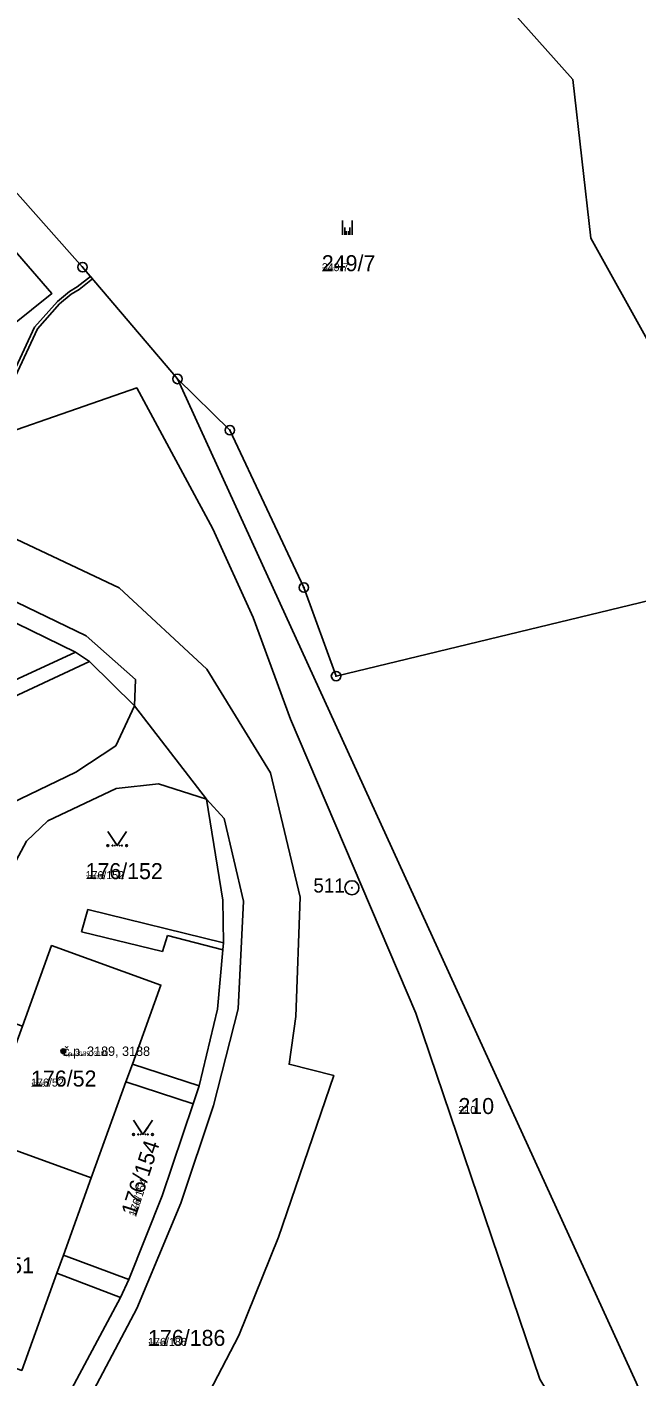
# Model space of a CAD drawing. Extents: x -759873 to -758487, y -975024 to -973516.
# Drawn here: x -759165.8 to -759101, y -974781.5 to -974638.1 of the extents above; entities that cross this region are included whole.
import ezdxf

# ---------------------------------------------------------------- set-up
doc = ezdxf.new("R2010")
doc.units = 0
for name, color, linetype in [('KAT_02_hranice parcel', 7, 'Continuous'), ('KAT_03_1000_st čísla parcelní', 7, 'Continuous'), ('KAT_03_1000_čísla parcelní', 7, 'Continuous'), ('KAT_03_1000_čísla popisná', 7, 'Continuous'), ('KAT_03_250_st čísla parcelní', 7, 'Continuous'), ('KAT_03_250_čísla parcelní', 7, 'Continuous'), ('KAT_03_250_čísla popisná', 7, 'Continuous'), ('KAT_03_500_st čísla parcelní', 7, 'Continuous'), ('KAT_03_500_čísla parcelní', 7, 'Continuous'), ('KAT_03_500_čísla popisná', 7, 'Continuous'), ('KAT_04_vnitřní kresba', 7, 'Continuous'), ('KAT_05_1000_značky kultur', 7, 'Continuous'), ('KAT_05_250_značky kultur', 7, 'Continuous'), ('KAT_05_500_značky kultur', 7, 'Continuous'), ('KAT_07_1000_značky budov', 7, 'Continuous'), ('KAT_07_250_značky budov', 7, 'Continuous'), ('KAT_07_500_značky budov', 7, 'Continuous'), ('KAT_10_věcná břemena', 7, 'Continuous'), ('KAT_11_značky bodu BP', 7, 'Continuous'), ('KAT_14_plocha_budovy', 7, 'Continuous'), ('KAT_14_plocha_pozemek', 7, 'Continuous')]:
    doc.layers.add(name, color=color, linetype=linetype)

msp = doc.modelspace()

# ---------------------------------------------------------------- linework, layer by layer
at = {"layer": 'KAT_02_hranice parcel'}
for p, q in [((-759179.67, -974713.25), (-759160.58, -974704.45)), ((-759159.12, -974705.45), (-759160.58, -974704.45)), ((-759159.12, -974705.45), (-759154.33, -974710.16)), ((-759154.33, -974710.16), (-759146.66, -974720.07)), ((-759148.07, -974752.44), (-759147.45, -974750.53)), ((-759158.92, -974760.3), (-759170.54, -974756.1)), ((-759155.8, -974773.02), (-759154.93, -974771.11))]:
    msp.add_line(p, q, dxfattribs=at)
for points in [[(-759121.31, -974628.39), (-759107.72, -974643.63), (-759105.8, -974660.49), (-759087.3, -974693.73), (-759084.37, -974695.3)], [(-759179.97, -974642.79), (-759178.7, -974648.26), (-759178.66, -974648.44), (-759163.12, -974666.36), (-759176.12, -974676.76)], [(-759149.76, -974675.44), (-759159.84, -974663.56), (-759172.86, -974648.93), (-759179.97, -974642.79)], [(-759084.37, -974695.3), (-759132.9, -974707), (-759136.32, -974697.59), (-759144.18, -974680.88), (-759149.76, -974675.44)], [(-759097.35, -974808.06), (-759096.43, -974792.71), (-759100.98, -974782.04), (-759149.76, -974675.44)], [(-759175.68, -974683.88), (-759154.09, -974676.39), (-759145.99, -974691.36), (-759141.71, -974700.76), (-759137.73, -974711.57), (-759124.4, -974742.82), (-759111.25, -974781.7), (-759103.79, -974793.94), (-759101.42, -974795.61)], [(-759182.08, -974824.14), (-759181.15, -974823.29), (-759171.83, -974813.43), (-759165.02, -974804.41), (-759157.43, -974793.66), (-759153.11, -974796.03), (-759143.25, -974777.05), (-759139.01, -974766.6), (-759133.15, -974749.42), (-759137.89, -974748.23), (-759137.17, -974743.17), (-759136.73, -974730.48), (-759139.87, -974717.29), (-759146.64, -974706.25), (-759155.94, -974697.62), (-759168.19, -974691.87), (-759181.09, -974689.78), (-759191.31, -974690.97), (-759198.55, -974692.98), (-759199.06, -974691.99)], [(-759160.58, -974704.45), (-759170.07, -974699.86), (-759180.57, -974698.08), (-759189.73, -974699.13), (-759195.81, -974700.76)], [(-759297.2, -974770.95), (-759269.53, -974757.78), (-759268.81, -974757.44), (-759237.44, -974742.52), (-759232.51, -974740.14), (-759189.23, -974719.52), (-759188.5, -974719.17), (-759159.12, -974705.45)], [(-759301.24, -974780.99), (-759301.03, -974781.35), (-759293.44, -974780.74), (-759288.26, -974778.87), (-759268.89, -974769.51), (-759250.85, -974760.82), (-759247.34, -974759.1), (-759236.73, -974753.99), (-759224.73, -974748.18), (-759206.51, -974739.34), (-759188.27, -974730.61), (-759177.27, -974725.26), (-759160.55, -974717.22), (-759156.31, -974714.42), (-759154.33, -974710.16)], [(-759146.66, -974720.07), (-759151.76, -974718.46), (-759156.28, -974718.94), (-759163.54, -974722.39), (-759165.81, -974724.55), (-759167.17, -974727.13)], [(-759147.45, -974750.53), (-759145.5, -974742.38), (-759144.92, -974736.07), (-759144.85, -974735.33), (-759144.92, -974730.81), (-759146.66, -974720.07)], [(-759147.45, -974750.53), (-759154.55, -974748.22), (-759151.52, -974739.83), (-759163.14, -974735.63), (-759166.23, -974744.18), (-759171.94, -974742.21)], [(-759158.92, -974760.3), (-759155.23, -974750.11), (-759148.07, -974752.44)], [(-759154.93, -974771.11), (-759151.37, -974762.2), (-759148.07, -974752.44)], [(-759154.93, -974771.11), (-759161.88, -974768.5), (-759158.92, -974760.3)], [(-759179.16, -974764.89), (-759174.26, -974766.42), (-759177.93, -974776.57), (-759166.31, -974780.76), (-759162.58, -974770.43), (-759155.8, -974773.02)], [(-759178.71, -974808.89), (-759171.77, -974799.76), (-759171.33, -974799.09), (-759163.17, -974786.79), (-759155.8, -974773.02)]]:
    msp.add_lwpolyline(points, dxfattribs=at)
at = {"layer": 'KAT_03_1000_čísla popisná'}
msp.add_circle((-759161.89, -974746.85), 0.25, dxfattribs=at)
at = {"layer": 'KAT_03_250_čísla popisná'}
msp.add_circle((-759161.89, -974746.85), 0.0625, dxfattribs=at)
at = {"layer": 'KAT_03_500_čísla popisná'}
msp.add_circle((-759161.89, -974746.85), 0.125, dxfattribs=at)
at = {"layer": 'KAT_04_vnitřní kresba'}
for p, q in [((-759169.64, -974697.85), (-759159.46, -974702.72)), ((-759159.46, -974702.72), (-759154.22, -974707.35)), ((-759154.33, -974710.16), (-759154.22, -974707.35)), ((-759146.66, -974720.07), (-759144.79, -974722.14)), ((-759144.79, -974722.14), (-759142.73, -974730.92)), ((-759143.3, -974742.35), (-759142.73, -974730.92)), ((-759159.94, -974734.16), (-759159.3, -974731.81)), ((-759159.3, -974731.81), (-759144.85, -974735.33)), ((-759159.94, -974734.16), (-759151.34, -974736.25)), ((-759151.34, -974736.25), (-759150.83, -974734.56)), ((-759150.83, -974734.56), (-759144.92, -974736.07)), ((-759145.92, -974752.61), (-759143.3, -974742.35)), ((-759155.23, -974750.11), (-759154.55, -974748.22)), ((-759149.41, -974762.99), (-759145.92, -974752.61)), ((-759154.08, -974774.19), (-759149.41, -974762.99)), ((-759162.58, -974770.43), (-759161.88, -974768.5)), ((-759161.31, -974787.79), (-759154.08, -974774.19))]:
    msp.add_line(p, q, dxfattribs=at)
at = {"layer": 'KAT_05_1000_značky kultur'}
for p, q in [((-759132.2, -974660.11), (-759132.2, -974658.61)), ((-759131.2, -974660.11), (-759131.2, -974658.61))]:
    msp.add_line(p, q, dxfattribs=at)
for points in [[(-759157.16, -974723.51), (-759156.16, -974725.01), (-759155.16, -974723.51)], [(-759154.42, -974754.19), (-759153.42, -974755.69), (-759152.42, -974754.19)]]:
    msp.add_lwpolyline(points, dxfattribs=at)
for centre in [(-759157.16, -974725.01), (-759155.16, -974725.01), (-759154.42, -974755.69), (-759152.42, -974755.69)]:
    msp.add_circle(centre, 0.1, dxfattribs=at)
at = {"layer": 'KAT_05_250_značky kultur'}
for p, q in [((-759131.82, -974660.11), (-759131.82, -974659.73)), ((-759131.57, -974660.11), (-759131.57, -974659.73))]:
    msp.add_line(p, q, dxfattribs=at)
for points in [[(-759156.41, -974724.63), (-759156.16, -974725.01), (-759155.91, -974724.63)], [(-759153.67, -974755.31), (-759153.42, -974755.69), (-759153.17, -974755.31)]]:
    msp.add_lwpolyline(points, dxfattribs=at)
for centre in [(-759156.41, -974725.01), (-759155.91, -974725.01), (-759153.67, -974755.69), (-759153.17, -974755.69)]:
    msp.add_circle(centre, 0.025, dxfattribs=at)
at = {"layer": 'KAT_05_500_značky kultur'}
for p, q in [((-759131.95, -974660.11), (-759131.95, -974659.36)), ((-759131.45, -974660.11), (-759131.45, -974659.36))]:
    msp.add_line(p, q, dxfattribs=at)
for points in [[(-759156.66, -974724.26), (-759156.16, -974725.01), (-759155.66, -974724.26)], [(-759153.92, -974754.94), (-759153.42, -974755.69), (-759152.92, -974754.94)]]:
    msp.add_lwpolyline(points, dxfattribs=at)
for centre in [(-759156.66, -974725.01), (-759155.66, -974725.01), (-759153.92, -974755.69), (-759152.92, -974755.69)]:
    msp.add_circle(centre, 0.05, dxfattribs=at)
at = {"layer": 'KAT_07_1000_značky budov'}
msp.add_circle((-759161.9, -974746.85), 0.175, dxfattribs=at)
at = {"layer": 'KAT_07_250_značky budov'}
msp.add_circle((-759161.89, -974746.85), 0.0437, dxfattribs=at)
at = {"layer": 'KAT_07_500_značky budov'}
msp.add_circle((-759161.89, -974746.85), 0.0875, dxfattribs=at)
at = {"layer": 'KAT_10_věcná břemena'}
msp.add_lwpolyline([(-759160.41, -974665.65), (-759161.25, -974666.14), (-759162.52, -974667.2), (-759164.95, -974669.93), (-759168.45, -974677.51), (-759169.21, -974679.17), (-759170.1, -974681.94), (-759169.7, -974681.8), (-759168.89, -974679.29), (-759168.13, -974677.65), (-759164.65, -974670.12), (-759162.29, -974667.47), (-759161.06, -974666.44), (-759160.19, -974665.93), (-759158.78, -974664.81), (-759159.01, -974664.54)], close=True, dxfattribs=at)
at = {"layer": 'KAT_11_značky bodu BP'}
for centre, radius in [((-759159.84, -974663.56), 0.5), ((-759159.84, -974663.56), 0.0303), ((-759149.76, -974675.44), 0.5), ((-759149.76, -974675.44), 0.0303), ((-759144.18, -974680.88), 0.5), ((-759144.18, -974680.88), 0.0303), ((-759136.32, -974697.59), 0.5), ((-759136.32, -974697.59), 0.0303), ((-759132.9, -974707), 0.5), ((-759132.9, -974707), 0.0303), ((-759131.21, -974729.49), 0.75), ((-759131.21, -974729.49), 0.03)]:
    msp.add_circle(centre, radius, dxfattribs=at)
at = {"layer": 'KAT_14_plocha_budovy'}
msp.add_lwpolyline([(-759154.55, -974748.22), (-759151.52, -974739.83), (-759163.14, -974735.63), (-759166.23, -974744.18), (-759166.93, -974746.13), (-759170.54, -974756.1), (-759173.59, -974764.55), (-759174.26, -974766.42), (-759177.93, -974776.57), (-759166.31, -974780.76), (-759162.58, -974770.43), (-759161.88, -974768.5), (-759158.92, -974760.3), (-759155.23, -974750.11)], close=True, dxfattribs=at)
at = {"layer": 'KAT_14_plocha_pozemek'}
for points in [[(-759179.97, -974642.79), (-759172.86, -974648.93), (-759159.84, -974663.56), (-759149.76, -974675.44), (-759144.18, -974680.88), (-759136.32, -974697.59), (-759132.9, -974707), (-759084.37, -974695.3), (-759087.3, -974693.73), (-759105.8, -974660.49), (-759107.72, -974643.63), (-759121.31, -974628.39), (-759134.04, -974629.13), (-759146.2, -974621.75), (-759148.58, -974619.46), (-759181.41, -974628.97), (-759180.71, -974639.63)], [(-759050.14, -974687.05), (-759051.77, -974677.63), (-759055.52, -974672.89), (-759062.41, -974666.25), (-759071.5, -974656.72), (-759078.54, -974653.94), (-759098.65, -974634.53), (-759100.6, -974632.63), (-759109.03, -974624.43), (-759119.5, -974620.56), (-759124.04, -974618.94), (-759121.31, -974628.39), (-759107.72, -974643.63), (-759105.8, -974660.49), (-759087.3, -974693.73), (-759084.37, -974695.3)], [(-759179.97, -974642.79), (-759182.75, -974640.39), (-759181.82, -974645.65), (-759180.9, -974650.86), (-759176.12, -974676.76), (-759163.12, -974666.36), (-759178.66, -974648.44), (-759178.7, -974648.26)], [(-759172.86, -974648.93), (-759179.97, -974642.79), (-759178.7, -974648.26), (-759178.66, -974648.44), (-759163.12, -974666.36), (-759176.12, -974676.76), (-759181.05, -974677.28), (-759181.59, -974677.34), (-759188.35, -974680.73), (-759175.68, -974683.88), (-759154.09, -974676.39), (-759145.99, -974691.36), (-759141.71, -974700.76), (-759137.73, -974711.57), (-759124.4, -974742.82), (-759111.25, -974781.7), (-759103.79, -974793.94), (-759101.42, -974795.61), (-759097.35, -974808.06), (-759096.43, -974792.71), (-759100.98, -974782.04), (-759149.76, -974675.44), (-759159.84, -974663.56)], [(-759136.32, -974697.59), (-759144.18, -974680.88), (-759149.76, -974675.44), (-759100.98, -974782.04), (-759096.43, -974792.71), (-759097.35, -974808.06), (-759093.87, -974828.86), (-759092.71, -974830.26), (-759063.93, -974793.72), (-759032.83, -974761.31), (-759037.71, -974733.96), (-759052.64, -974724.43), (-759065.6, -974705.35), (-759084.37, -974695.3), (-759132.9, -974707)], [(-759160.58, -974704.45), (-759170.07, -974699.86), (-759180.57, -974698.08), (-759189.73, -974699.13), (-759195.81, -974700.76), (-759193.24, -974705.96), (-759184.99, -974702.09), (-759179.67, -974713.25)], [(-759189.23, -974719.52), (-759188.5, -974719.17), (-759159.12, -974705.45), (-759160.58, -974704.45), (-759179.67, -974713.25), (-759199.38, -974722.66), (-759219.12, -974732.06), (-759238.84, -974741.43), (-759258.52, -974750.77), (-759278.22, -974760.18), (-759297.83, -974769.65), (-759297.2, -974770.95), (-759269.53, -974757.78), (-759268.81, -974757.44), (-759237.44, -974742.52), (-759232.51, -974740.14)], [(-759145.5, -974742.38), (-759144.92, -974736.07), (-759144.85, -974735.33), (-759144.92, -974730.81), (-759146.66, -974720.07), (-759151.76, -974718.46), (-759156.28, -974718.94), (-759163.54, -974722.39), (-759165.81, -974724.55), (-759167.17, -974727.13), (-759171.94, -974742.21), (-759166.23, -974744.18), (-759163.14, -974735.63), (-759151.52, -974739.83), (-759154.55, -974748.22), (-759147.45, -974750.53)], [(-759163.14, -974735.63), (-759166.23, -974744.18), (-759171.94, -974742.21), (-759172.57, -974744.14), (-759166.93, -974746.13), (-759170.54, -974756.1), (-759158.92, -974760.3), (-759155.23, -974750.11), (-759148.07, -974752.44), (-759147.45, -974750.53), (-759154.55, -974748.22), (-759151.52, -974739.83)], [(-759151.37, -974762.2), (-759148.07, -974752.44), (-759155.23, -974750.11), (-759158.92, -974760.3), (-759161.88, -974768.5), (-759154.93, -974771.11)], [(-759166.31, -974780.76), (-759162.58, -974770.43), (-759155.8, -974773.02), (-759154.93, -974771.11), (-759161.88, -974768.5), (-759158.92, -974760.3), (-759170.54, -974756.1), (-759173.59, -974764.55), (-759178.54, -974762.94), (-759179.16, -974764.89), (-759174.26, -974766.42), (-759177.93, -974776.57)], [(-759171.77, -974799.76), (-759171.33, -974799.09), (-759163.17, -974786.79), (-759155.8, -974773.02), (-759162.58, -974770.43), (-759166.31, -974780.76), (-759177.93, -974776.57), (-759174.26, -974766.42), (-759179.16, -974764.89), (-759180.75, -974769.83), (-759182.55, -974773.33), (-759188.7, -974782.52), (-759191.81, -974786.42), (-759196.78, -974791.27), (-759193.36, -974794.78), (-759186.79, -974788.35), (-759178.14, -974797.19), (-759184.5, -974803.41), (-759178.71, -974808.89)]]:
    msp.add_lwpolyline(points, close=True, dxfattribs=at)
for points in [[(-759111.25, -974781.7), (-759124.4, -974742.82), (-759137.73, -974711.57), (-759141.71, -974700.76), (-759145.99, -974691.36), (-759154.09, -974676.39), (-759175.68, -974683.88), (-759195.03, -974690.6), (-759199.06, -974691.99), (-759198.55, -974692.98), (-759191.31, -974690.97), (-759181.09, -974689.78), (-759168.19, -974691.87), (-759155.94, -974697.62), (-759146.64, -974706.25), (-759139.87, -974717.29), (-759136.73, -974730.48), (-759137.17, -974743.17), (-759137.89, -974748.23), (-759133.15, -974749.42), (-759139.01, -974766.6), (-759143.25, -974777.05), (-759153.11, -974796.03)], [(-759153.11, -974796.03), (-759143.25, -974777.05), (-759139.01, -974766.6), (-759133.15, -974749.42), (-759137.89, -974748.23), (-759137.17, -974743.17), (-759136.73, -974730.48), (-759139.87, -974717.29), (-759146.64, -974706.25), (-759155.94, -974697.62), (-759168.19, -974691.87)], [(-759170.07, -974699.86), (-759160.58, -974704.45), (-759159.12, -974705.45), (-759154.33, -974710.16), (-759146.66, -974720.07), (-759144.92, -974730.81), (-759144.85, -974735.33), (-759144.92, -974736.07), (-759145.5, -974742.38), (-759147.45, -974750.53), (-759148.07, -974752.44), (-759151.37, -974762.2), (-759154.93, -974771.11), (-759155.8, -974773.02), (-759163.17, -974786.79)], [(-759177.27, -974725.26), (-759160.55, -974717.22), (-759156.31, -974714.42), (-759154.33, -974710.16), (-759159.12, -974705.45), (-759188.5, -974719.17)], [(-759165.81, -974724.55), (-759163.54, -974722.39), (-759156.28, -974718.94), (-759151.76, -974718.46), (-759146.66, -974720.07), (-759154.33, -974710.16), (-759156.31, -974714.42), (-759160.55, -974717.22), (-759177.27, -974725.26)]]:
    msp.add_lwpolyline(points, dxfattribs=at)

# ---------------------------------------------------------------- texts
at = {"layer": 'KAT_03_1000_st čísla parcelní'}
for s, p in [('176/52', (-759165.32, -974750.6)), ('176/51', (-759171.96, -974770.43))]:
    msp.add_text(s, height=1.7, dxfattribs=at).set_placement(p)
at = {"layer": 'KAT_03_1000_čísla parcelní'}
for s, p in [('249/7', (-759134.41, -974663.99)), ('176/152', (-759159.53, -974728.57)), ('210', (-759119.89, -974753.52)), ('176/186', (-759152.88, -974778.15))]:
    msp.add_text(s, height=1.7, dxfattribs=at).set_placement(p)
msp.add_text('176/154', height=1.7, rotation=72, dxfattribs=at).set_placement((-759154.17, -974764.48))
at = {"layer": 'KAT_03_1000_čísla popisná'}
msp.add_text('č.p. 3189, 3188', height=1, dxfattribs=at).set_placement((-759161.89, -974747.35))
at = {"layer": 'KAT_03_250_st čísla parcelní'}
msp.add_text('176/52', height=0.425, dxfattribs=at).set_placement((-759165.32, -974750.6))
at = {"layer": 'KAT_03_250_čísla parcelní'}
for s, p in [('249/7', (-759134.41, -974663.99)), ('176/152', (-759159.53, -974728.57)), ('210', (-759119.89, -974753.52)), ('176/186', (-759152.88, -974778.15))]:
    msp.add_text(s, height=0.425, dxfattribs=at).set_placement(p)
msp.add_text('176/154', height=0.425, rotation=72, dxfattribs=at).set_placement((-759154.17, -974764.48))
at = {"layer": 'KAT_03_250_čísla popisná'}
msp.add_text('č.p. 3189, 3188', height=0.25, dxfattribs=at).set_placement((-759161.89, -974747.35))
at = {"layer": 'KAT_03_500_st čísla parcelní'}
msp.add_text('176/52', height=0.85, dxfattribs=at).set_placement((-759165.32, -974750.6))
at = {"layer": 'KAT_03_500_čísla parcelní'}
for s, p in [('249/7', (-759134.41, -974663.99)), ('176/152', (-759159.53, -974728.57)), ('210', (-759119.89, -974753.52)), ('176/186', (-759152.88, -974778.15))]:
    msp.add_text(s, height=0.85, dxfattribs=at).set_placement(p)
msp.add_text('176/154', height=0.85, rotation=72, dxfattribs=at).set_placement((-759154.17, -974764.48))
at = {"layer": 'KAT_03_500_čísla popisná'}
msp.add_text('č.p. 3189, 3188', height=0.5, dxfattribs=at).set_placement((-759161.89, -974747.35))
at = {"layer": 'KAT_11_značky bodu BP'}
msp.add_text('511', height=1.5, dxfattribs=at).set_placement((-759135.31, -974729.99))

doc.saveas('drawing.dxf')
